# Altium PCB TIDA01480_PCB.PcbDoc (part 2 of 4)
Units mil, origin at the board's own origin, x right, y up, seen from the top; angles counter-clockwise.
Board outline 2500 x 3500 mil, 6 copper layers (Top Layer, GND Upper, Signal Layer 1, Signal Layer 2, GND Lower, Bottom Layer), stack 63.4 mil thick; 332 components, 140 nets, 983 pads, 692 vias.
Unrouted connection lines stored in the file: 17.
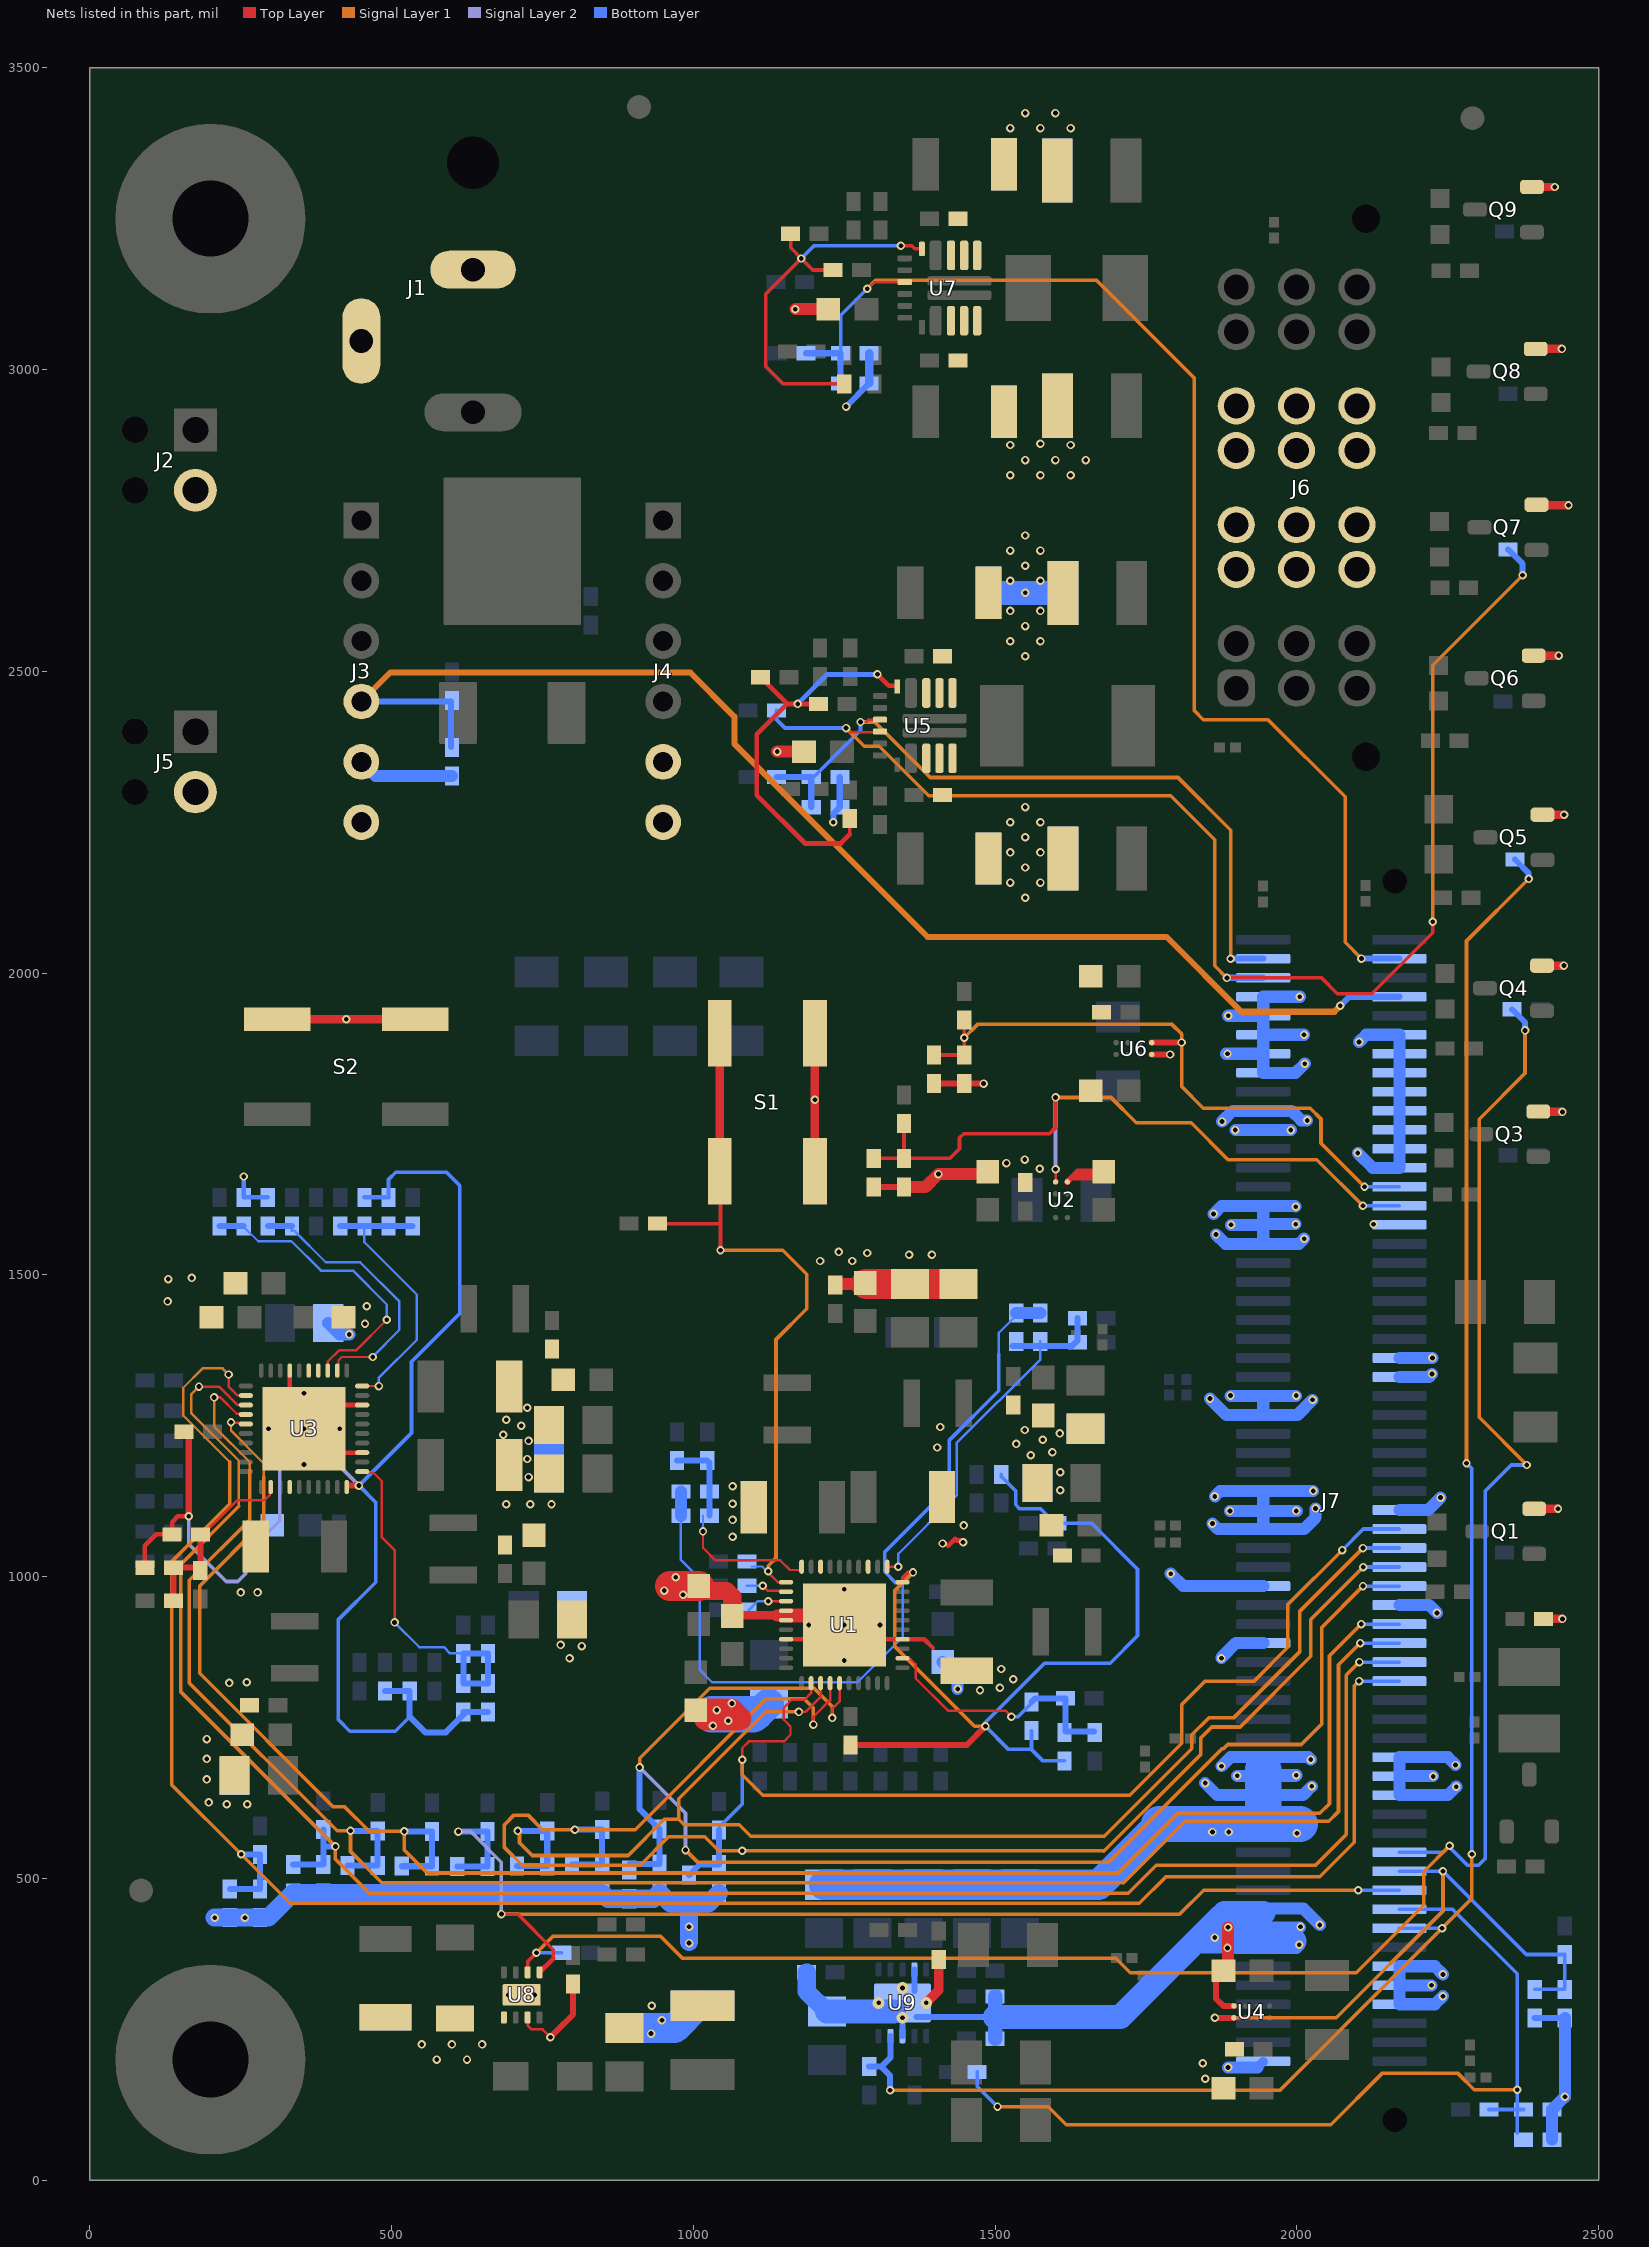
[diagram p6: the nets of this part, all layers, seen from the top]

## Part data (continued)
C7 C32 C114 C115: library part CMP-0006824-2, "CAP, CERM, 1 uF, 16 V, +/- 20%, X5R, 0603", Cap_Case=0603, Manufacturer="Wurth Elektronik", Supplier Part Number 1=710-885012106017, TempCo=X5R, Tolerance_%=20%, Value1=Unknown, Value2=16V, ValueDisplayed=1uF
C8 C12 C13 C33 C34 C35 C52 C53 C54 C55 C69 C70 C71 C72 C82 C83: library part CMP-0009116-1, "CAP, CERM, 22 uF, 16 V, +/- 10%, X7R, 1210", Cap_Case=1210_280, Manufacturer=TDK, Supplier Part Number 1=445-3945-1-ND, TempCo=X7R, Tolerance_%=10%, Value1="0.002582 ohm", Value2=16V, ValueDisplayed=22uF
C10 C41 C65: library part CMP-0064927-2, "CAP, CERM, 1 uF, 10 V,+/- 20%, X5R, 0402", Cap_Case=0402, Manufacturer=MuRata, Supplier Part Number 1=490-5409-1-ND, TempCo=X5R, Tolerance_%=20%, Value1=Unknown, Value2=10V, ValueDisplayed=1uF
C11 C42 C66: library part CMP-0007503-3, "CAP, CERM, 4.7 uF, 6.3 V, +/- 10%, X7R, 0603", Cap_Case=0603, Manufacturer="Taiyo Yuden", TempCo=X7R, Tolerance_%=10%, Value1=Unknown, Value2=6.3V, ValueDisplayed=4.7uF
C22 C47: library part CMP-0006678-2, "CAP, CERM, 1500 pF, 50 V, +/- 10%, X7R, 0402", Cap_Case=0402, Manufacturer=MuRata, Supplier Part Number 1=490-3245-1-ND, TempCo=X7R, Tolerance_%=10%, Value1=Unknown, Value2=50V, ValueDisplayed=1500pF
C25 C50: library part CMP-0007690-2, "CAP, CERM, 4.7 uF, 10 V, +/- 10%, X7R, 0805", Cap_Case=0805, Manufacturer="Wurth Elektronik", Supplier Part Number 1=710-885012207025, TempCo=X7R, Tolerance_%=10%, Value1=Unknown, Value2=10V, ValueDisplayed=4.7uF
C51 C56 C57 C68 C73 C74: library part CMP-0006295-2, "CAP, CERM, 0.1 uF, 25 V, +/- 20%, X7R, 0402", Cap_Case=0402, Manufacturer=TDK, Supplier Part Number 1=445-7349-1-ND, TempCo=X7R, Tolerance_%=20%, Value1=Unknown, Value2=25V, ValueDisplayed=0.1uF
C58 C59 C60 C61 C75 C76 C77 C78 C90 C91: library part CMP-0009220-2, "CAP, CERM, 47 uF, 10 V, +/- 10%, X7R, 1210", Cap_Case=1210, Manufacturer=MuRata, Supplier Part Number 1=490-5312-1-ND, TempCo=X7R, Tolerance_%=10%, Value1=Unknown, Value2=10V, ValueDisplayed=47uF
C62 C79: library part CMP-0006388-2, "CAP, CERM, 47 pF, 25 V, +/- 5%, C0G/NP0, 0402", Cap_Case=0402, Manufacturer=MuRata, Supplier Part Number 1=81-GRM1555C1E470JA1D, TempCo=C0G/NP0, Tolerance_%=5%, Value1=Unknown, Value2=25V, ValueDisplayed=47pF
C63 C80: library part CMP-0007105-5, "CAP, CERM, 4.7 uF, 10 V, +/- 10%, X5R, 0603", Cap_Case=0603, Manufacturer=TDK, Supplier Part Number 1=445-7482-1-ND, TempCo=X5R, Tolerance_%=10%, Value1=Unknown, Value2=10V, ValueDisplayed=4.7uF
C67 C81: library part CMP-0006298-2, "CAP, CERM, 0.047 uF, 50 V, +/- 10%, X7R, 0402", Cap_Case=0402, Manufacturer=TDK, Supplier Part Number 1=445-7336-1-ND, TempCo=X7R, Tolerance_%=10%, Value1="0.06407 ohm", Value2=50V, ValueDisplayed=0.047uF
C84: library part CMP-0008692-2, "CAP, CERM, 10 uF, 25 V, +/- 20%, X7R, 1206_190", Cap_Case=1206, Manufacturer=TDK, Supplier Part Number 1=445-6812-1-ND, TempCo=X7R, Tolerance_%=20%, Value1=Unknown, Value2=25V, ValueDisplayed=10uF
C85 C86 C87 C97 C98: library part CMP-0008311-2, "CAP, CERM, 10 uF, 6.3 V, +/- 10%, X7R, 0805", Cap_Case=0805, Manufacturer=MuRata, Supplier Part Number 1=490-3904-1-ND, TempCo=X7R, Tolerance_%=10%, Value1=Unknown, Value2=6.3V, ValueDisplayed=10uF
C92: library part CMP-0008283-2, "CAP, CERM, 4.7 uF, 6.3 V, +/- 10%, X5R, 0805", Cap_Case=0805, Manufacturer=MuRata, Supplier Part Number 1=GRM21BR60J475KA11L-ND, TempCo=X5R, Tolerance_%=10%, Value1=Unknown, Value2=6.3V, ValueDisplayed=4.7uF
C93: library part CMP-0006348-2, "CAP, CERM, 22 pF, 50 V, +/- 5%, C0G/NP0, AEC-Q200 Grade 1, 0402", Cap_Case=0402, Manufacturer=MuRata, Supplier Part Number 1=490-9648-1-ND, TempCo=C0G/NP0, Tolerance_%=5%, Value1=Unknown, Value2=50V, ValueDisplayed=22pF
C94: library part CMP-0006408-2, "CAP, CERM, 10 pF, 50 V, +/- 5%, C0G/NP0, 0402", Cap_Case=0402, Manufacturer=MuRata, Supplier Part Number 1=81-GRM1555C1H100JA1D, TempCo=C0G/NP0, Tolerance_%=5%, Value1=Unknown, Value2=50V, ValueDisplayed=10pF
C96: library part CMP-0006296-2, "CAP, CERM, 1000 pF, 50 V, +/- 20%, X7R, 0402", Cap_Case=0402, Manufacturer=TDK, Supplier Part Number 1=445-173775-1-ND, TempCo=X7R, Tolerance_%=20%, Value1=Unknown, Value2=50V, ValueDisplayed=1000pF
C99 C100 C101 C102: library part CMP-0006406-2, "CAP, CERM, 910 pF, 25 V, +/- 5%, C0G/NP0, 0402", Cap_Case=0402, Manufacturer=MuRata, Supplier Part Number 1=GRM1555C1E911JA01D-ND, TempCo=C0G/NP0, Tolerance_%=5%, Value1=Unknown, Value2=25V, ValueDisplayed=910pF
C103 C106 C107: library part CMP-0006393-2, "CAP, CERM, 510 pF, 25 V, +/- 5%, C0G/NP0, 0402", Cap_Case=0402, Manufacturer=MuRata, Supplier Part Number 1=GRM1555C1E511JA01D-ND, TempCo=C0G/NP0, Tolerance_%=5%, Value1=Unknown, Value2=25V, ValueDisplayed=510pF
C104 C108 C111 C112: library part CMP-0006410-2, "CAP, CERM, 100 pF, 50 V, +/- 5%, C0G/NP0, 0402", Cap_Case=0402, Manufacturer=MuRata, Supplier Part Number 1=81-GRM1555C1H101JA1D, TempCo=C0G/NP0, Tolerance_%=5%, Value1=Unknown, Value2=50V, ValueDisplayed=100pF
C105 C109 C110 C113: library part CMP-0064916-2, "CAP, CERM, 10 pF, 50 V,+/- 1%, C0G/NP0, 0402", Cap_Case=0402, Manufacturer=MuRata, Supplier Part Number 1=490-6186-1-ND, TempCo=C0G/NP0, Tolerance_%=1%, Value1=Unknown, Value2=50V, ValueDisplayed=10pF
D1: library part CMP-0028356-1, "Diode, Schottky, 40 V, 12 A, DPAK", Manufacturer=Vishay-Semiconductor, Supplier Part Number 1=844-12CWQ04FNPBF, Value1=12A, Value2=0.68V
D2: library part CMP-0002884-1, "LED, Cool White, SMD", Color="cool white", Manufacturer=Panasonic, Supplier Part Number 1=LNJ037X8ARACT-ND, Value1=W, Value2=2.9V
D3: library part CMP-0067668-1, "LED, Red, SMD", Color=Red, Manufacturer=Vishay-Semiconductor, Power_TotalModule=200mW, Supplier Part Number 1=VLMR334BACB-GS08CT-ND, Value1=0.2W, Value2=2.2V
D4 D7 D8 D9 D10: "LED, Green, SMD", Color=green, Manufacturer=Lite-On, Supplier Part Number 1=160-1435-1-ND, Value1=W, Value2=2V
D5: "LED, Orange, SMD", Color=orange, Manufacturer=Lite-On, Power_TotalModule=0.075, Supplier Part Number 1=160-1434-1-ND, Value1=0.075W, Value2=2V
D6: library part CMP-0002862-1, "LED, Yellow , SMD", Color=yellow, Manufacturer=Lite-On, Supplier Part Number 1=160-1416-1-ND, Value1=W, Value2=2V
FID1 FID2 FID3: "Fiducial mark.  There is nothing to buy or mount.", Manufacturer=N/A
H1 H2: "Machine Screw, Round, #4-40 x 1/4, Nylon, Philips panhead", DigiKeyPartNumber=H542-ND, Manufacturer="B&F Fastener Supply"
H3 H4: "Standoff, Hex, 0.5\"L #4-40 Nylon", Manufacturer=Keystone, Supplier Part Number 1=36-1902C-ND
J1: library part CMP-0075310-1, "Connector, DC Jack 2.5 mm Center Pin, TH", Color=Black, Current_A=2.5A, Manufacturer="CUI Inc.", Supplier Part Number 1=CP-058B-ND, Voltage_V=24V
J2 J5: library part CMP-0055479-1, "Terminal Block, 100mil, 2x1, 6A, 63V, TH", Manufacturer="Phoenix Contact", Supplier Part Number 1=71C4107
J3 J4: library part CMP-0055084-1, "Header, 100mil, 6x1, TH", Manufacturer=Mill-Max, Supplier Part Number 1=ED7206-ND
J6: library part CMP-0078461-1, "Receptacle, 5mm, 4x1, Gold with Tin tail, TH", Color=Black, Current_A=30A, Manufacturer=Samtec, Supplier Part Number 1=SAM9721-ND, Voltage_V=812V
J7: library part CMP-0078459-1, "Socket Assembly, 0.8mm, 60x2, Gold, SMT", Color=Black, Manufacturer=Samtec, Supplier Part Number 1=SAM9181-ND
L1 L2 L3 L4 L5 L6: library part CMP-0062881-1, "Inductor, Film, 2.2 uH, 2.6 A, 0.084 ohm, AEC-Q200 Grade 0, SMD", Manufacturer=TDK, Value1="0.084 ohm", Value2=2.6A, ValueDisplayed=2.2uH
L7: library part CMP-0063396-1, "Inductor, Shielded Drum Core, Powdered Iron, 470 nH, 17.5 A, 0.004 ohm, SMD", Manufacturer=Vishay-Dale, Supplier Part Number 1=541-1003-1-ND, Value1="0.004 ohm", Value2=17.5A, ValueDisplayed=470nH
L8: library part CMP-0063307-1, "Inductor, Shielded Drum Core, Powdered Iron, 470 nH, 11.5 A, 0.0081 ohm, SMD", Manufacturer=Vishay-Dale, Supplier Part Number 1=541-1085-1-ND, Value1="0.0081 ohm", Value2=11.5A, ValueDisplayed=470nH
L9: library part CMP-0063238-1, "Inductor, Shielded Drum Core, Powdered Iron, 1 uH, 3 A, 0.038 ohm, SMD", Manufacturer=Vishay-Dale, Value1="0.038 ohm", Value2=3A, ValueDisplayed=1uH
Logo1: library part TI_Logo, "Texas Instrument Corporate Signature"
Logo2: library part Pb-Free
Logo3: library part FCC_disclaimer, "FCC_disclaimer"
Q1 Q3 Q4 Q5 Q6 Q7 Q8 Q9: "MOSFET, N-CH, 60V, 0.17A, SOT-23", Alternate Manufacturer=None, Manufacturer="Diodes Inc.", Supplier Part Number 1=2N7002-FDICT-ND, Value1="7.5 ohm", Value2="223 nC"
Q2: library part CMP-0000011-2, "MOSFET, P-CH, -50 V, -0.13 A, SOT-23", Alternate Manufacturer=None, Manufacturer="Diodes Inc.", Supplier Part Number 1=BSS84-FDICT-ND
R1 R30: library part CMP-0025963-2, "RES, 10.0, 1%, 0.063 W, 0402", Manufacturer=Vishay-Dale, Power_W=63mW, Supplier Part Number 1=541-10.0LCT-ND, TempCo="100 ppm/C", Tolerance_%=1%, Value2=0.063W, Value_Code=10R0, ValueDisplayed=10.0
R2 R33 R62 R66 R67 R68 R69 R70 R71 R78 R135 R136: library part CMP-0018573-2, "RES, 0, 5%, 0.25 W, 1206", Manufacturer=Vishay-Dale, Power_W=250mW, Supplier Part Number 1=541-0.0ECT-ND, TempCo="200 ppm/C", Tolerance_%=5%, Value2=0.25W, Value_Code=0000, ValueDisplayed=0
R3 R4 R31 R32: library part CMP-0026952-4, "RES, 5.6 k, 5%, 0.063 W, 0402", Manufacturer=Vishay-Dale, Power_W=63mW, Supplier Part Number 1=541-5.6KJCT-ND, TempCo="200 ppm/C", Tolerance_%=5%, Value2=0.063W, Value_Code=5k60, ValueDisplayed=5.6k
R5 R6 R18 R19 R20 R25 R27 R28 R36 R37 R39 R41 R51 R52 R53 R57 R58 R59: library part CMP-0026964-2, "RES, 68, 5%, 0.063 W, 0402", Manufacturer=Vishay-Dale, Power_W=63mW, Supplier Part Number 1=541-68JCT-ND, TempCo="200 ppm/C", Tolerance_%=5%, Value2=0.063W, Value_Code=68R0, ValueDisplayed=68
R7: library part CMP-0025959-2, "RES, 10.2 k, 1%, 0.063 W, 0402", Manufacturer=Vishay-Dale, Power_W=63mW, Supplier Part Number 1=541-10.2KLCT-ND, TempCo="100 ppm/C", Tolerance_%=1%, Value2=0.063W, Value_Code=10k2, ValueDisplayed=10.2k
R8 R10 R38 R43 R82 R84 R87 R88 R89 R94 R99 R156: library part CMP-0026823-2, "RES, 100 k, 5%, 0.063 W, 0402", Manufacturer=Vishay-Dale, Power_W=63mW, Supplier Part Number 1=541-100KJCT-ND, TempCo="200 ppm/C", Tolerance_%=5%, Value2=0.063W, Value_Code=100k
R9 R15 R22 R23 R26 R35 R42 R48 R55 R63 R74: library part CMP-0026815-1, "RES, 100 k, 0.1%, 0.063 W, 0402", Manufacturer="Susumu Co Ltd", Power_W=63mW, Supplier Part Number 1=RG10P100KBCT-ND, TempCo="25 ppm/C", Tolerance_%=0.1%, Value2=0.063W, Value_Code=100k
R11 R12 R13 R14 R44 R45 R46 R47 R60 R72 R80 R90 R91 R92 R95 R96 R100 R155: library part CMP-0026825-4, "RES, 10 k, 5%, 0.063 W, 0402", Manufacturer=Vishay-Dale, Power_W=63mW, Supplier Part Number 1=541-10KJCT-ND, TempCo="200 ppm/C", Tolerance_%=5%, Value2=0.063W, Value_Code=10k0, ValueDisplayed=10k
R16 R49 R54 R56: library part CMP-0026158-1, "RES, 200 k, 1%, 0.063 W, 0402", Manufacturer=Vishay-Dale, Power_W=63mW, Supplier Part Number 1=541-200KLCT-ND, TempCo="100 ppm/C", Tolerance_%=1%, Value2=0.063W, Value_Code=200k
R17: library part CMP-0026176-1, "RES, 226 k, 1%, 0.063 W, 0402", Manufacturer=Vishay-Dale, Power_W=63mW, Supplier Part Number 1=541-226KLCT-ND, TempCo="100 ppm/C", Tolerance_%=1%, Value2=0.063W, Value_Code=226k
R21: library part CMP-0026288-1, "RES, 316 k, 1%, 0.063 W, 0402", Manufacturer=Vishay-Dale, Power_W=63mW, Supplier Part Number 1=541-316KLCT-ND, TempCo="100 ppm/C", Tolerance_%=1%, Value2=0.063W, Value_Code=316k
R24 R61 R73: library part CMP-0026702-1, "RES, 49.9 k, 1%, 0.1 W, AEC-Q200 Grade 0, 0402", Manufacturer=Panasonic, Power_W=100mW, Supplier Part Number 1=P49.9KLCT-ND, TempCo="100 ppm/C", Tolerance_%=1%, Value2=0.1W, Value_Code=49k9, ValueDisplayed=49.9k
R29 R81 R85 R93 R97 R98 R101: library part CMP-0026822-2, "RES, 0, 5%, 0.063 W, 0402", Manufacturer=Vishay-Dale, Power_W=63mW, Supplier Part Number 1=541-0.0JCT-ND, TempCo="200 ppm/C", Tolerance_%=5%, Value2=0.063W, Value_Code=0000, ValueDisplayed=0
R34: library part CMP-0026196-1, "RES, 24.9 k, 1%, 0.063 W, 0402", Manufacturer=Vishay-Dale, Power_W=63mW, Supplier Part Number 1=541-24.9KLCT-ND, TempCo="100 ppm/C", Tolerance_%=1%, Value2=0.063W, Value_Code=24k9, ValueDisplayed=24.9k
R40: library part CMP-0026502-1, "RES, 66.5 k, 1%, 0.063 W, 0402", Manufacturer=Vishay-Dale, Power_W=63mW, Supplier Part Number 1=541-66.5KLCT-ND, TempCo="100 ppm/C", Tolerance_%=1%, Value2=0.063W, Value_Code=66k5, ValueDisplayed=66.5k
R50: library part CMP-0026789-1, "RES, 86.6 k, 0.1%, 0.063 W, AEC-Q200 Grade 0, 0402", Manufacturer=Panasonic, Power_W=63mW, Supplier Part Number 1=P86.6KDCCT-ND, TempCo="25 ppm/C", Tolerance_%=0.1%, Value2=0.063W, Value_Code=86k6, ValueDisplayed=86.6k
R64 R65 R75 R76: library part CMP-0026437-1, "RES, 51.1 k, 1%, 0.063 W, 0402", Manufacturer=Vishay-Dale, Power_W=63mW, Supplier Part Number 1=541-51.1KLCT-ND, TempCo="100 ppm/C", Tolerance_%=1%, Value2=0.063W, Value_Code=51k1, ValueDisplayed=51.1k
R77 R79: library part CMP-0065360-1, "RES, 10.0 k, .1%, .0625 W, 0402", Manufacturer="Yageo America", Power_W=62.5mW, Supplier Part Number 1=YAG1346CT-ND, TempCo="25 ppm/C", Tolerance_%=0.1%, Value1=.1%, Value2=.0625W, Value_Code=10k0, ValueDisplayed=10.0k
R83: library part CMP-0026712-1, "RES, 97.6 k, 1%, 0.1 W, AEC-Q200 Grade 0, 0402", Manufacturer=Panasonic, Power_W=100mW, Supplier Part Number 1=P97.6KLCT-ND, TempCo="100 ppm/C", Tolerance_%=1%, Value2=0.1W, Value_Code=97k6, ValueDisplayed=97.6k
R86: library part CMP-0026787-1, "RES, 76.8 k, 0.1%, 0.063 W, AEC-Q200 Grade 0, 0402", Manufacturer=Panasonic, Power_W=63mW, Supplier Part Number 1=P76.8KDCCT-ND, TempCo="25 ppm/C", Tolerance_%=0.1%, Value2=0.063W, Value_Code=76k8, ValueDisplayed=76.8k
R102 R103 R104 R105 R106 R107 R108 R109 R110 R111 R112 R113 R114 R115 R116 R157: library part CMP-0026859-1, "RES, 1.0 M, 5%, 0.063 W, 0402", Manufacturer=Vishay-Dale, Power_W=63mW, Supplier Part Number 1=541-1.0MJCT-ND, TempCo="200 ppm/C", Tolerance_%=5%, Value2=0.063W, Value_Code=1M00, ValueDisplayed=1.0M
R117: library part CMP-0026882-2, "RES, 240, 5%, 0.063 W, 0402", Manufacturer=Vishay-Dale, Power_W=63mW, Supplier Part Number 1=541-240JCT-ND, TempCo="200 ppm/C", Tolerance_%=5%, Value2=0.063W, Value_Code=240R, ValueDisplayed=240
R118: library part CMP-0078194-1, "RES, 360, 5%, 0.1 W, AEC-Q200 Grade 0, 0402", Manufacturer=Panasonic, Power_W=100mW, Supplier Part Number 1=P360JCT-ND, TempCo="200 ppm/C", Tolerance_%=5%, Value2=0.1W, Value_Code=360R, ValueDisplayed=360
R119 R120 R122 R129 R130 R131: library part CMP-0026841-2, "RES, 150, 5%, 0.063 W, 0402", Manufacturer=Vishay-Dale, Power_W=63mW, Supplier Part Number 1=541-150JCT-ND, TempCo="200 ppm/C", Tolerance_%=5%, Value2=0.063W, Value_Code=150R, ValueDisplayed=150
R121: library part CMP-0026845-2, "RES, 160, 5%, 0.063 W, 0402", Manufacturer=Vishay-Dale, Power_W=63mW, Supplier Part Number 1=541-160JCT-ND, TempCo="200 ppm/C", Tolerance_%=5%, Value2=0.063W, Value_Code=160R, ValueDisplayed=160
R123 R124 R125 R126 R127 R128 R132 R133 R134: library part CMP-0027004-2, "RES, 0, 5%, 0.063 W, 0402", Manufacturer="Yageo America", Power_W=63mW, Supplier Part Number 1=311-0.0JRCT-ND, TempCo="200 ppm/C", Tolerance_%=5%, Value2=0.063W, Value_Code=0000, ValueDisplayed=0
R137 R138 R139 R140 R141 R142 R143 R144 R145 R146 R147 R148 R149 R150 R151 R152 R153 R154: library part CMP-0027008-3, "RES, 0, 5%, 0.05 W, 0201", Manufacturer=Vishay-Dale, Power_W=50mW, Supplier Part Number 1=72M6743, TempCo=ppm/C, Tolerance_%=5%, Value2=0.05W, Value_Code=0000, ValueDisplayed=0
S1 S2: library part CMP-0002132-2, "Switch, Tactile, SPST-NO, SMT", CurrentRating_mA=50A, Manufacturer="C&K Components", Supplier Part Number 1=401-1848-1-ND
U1 U3: library part CMP-0074190-1, "6-channel Power Management IC (PMIC) with 3DC/DCs, 3 LDOs, I2C Interface and DVS, RSB0040B (WQFN-40)", Alternate Manufacturer="Texas Instruments", Alternate PartNumber=TPS65023BRSBT
U2 U4 U6: library part CMP-0066647-2, "3.6V, 4A, 5.3mO Load Switch with Quick Output Discharge, YZP0008ADCD (DSBGA-8)", Alternate Manufacturer="Texas Instruments", Alternate PartNumber=TPS22920YZPT
U5: library part CMP-0074013-1, "4.5V to 17V Input, DCAP3 Mode, 12A Synchronous Step-Down SWIFT(TM) Converter, RNN0018A (VQFN-HR-18)", Alternate Manufacturer="Texas Instruments", Alternate PartNumber=TPS56C215RNNT
U7: library part CMP-0074010-1, "4.5V to 17V Input, DCAP3 Mode, 8A Synchronous SWIFT(TM) Step-Down Converter, RNN0018A (VQFN-HR-18)", Alternate Manufacturer="Texas Instruments", Alternate PartNumber=TPS568215RNNT
U8: library part CMP-0037738-2, "Buck Step Down Regulator with 2.9 to 6 V Input and 0.8 to 6 V Output, -40 to 85 degC, 8-Pin WSON (DSG), Green (RoHS & no Sb/Br)", Manufacturer="Texas Instruments", Rating=Catalog, Switch Current Limit(Typ)(A)=2.75
U9: library part CMP-0036438-2, "Single Output LDO, 3 A, 2.375 to 3.5 V Input, with DDR Termination, 10-pin SON (DRC), -40 to 85 degC, Green (RoHS & no Sb/Br)", Manufacturer="Texas Instruments", Power Good=TRUE, Rating=Catalog
ZZ1: library part AssemblyNoteLabel
ZZ2 ZZ3 ZZ4: library part AssemblyNote

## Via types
v1: diameter 14, hole 7.9, Top Layer to Bottom Layer, tented both sides, 676 vias
v2: diameter 19.68, hole 7.87, Top Layer to Bottom Layer, 16 vias

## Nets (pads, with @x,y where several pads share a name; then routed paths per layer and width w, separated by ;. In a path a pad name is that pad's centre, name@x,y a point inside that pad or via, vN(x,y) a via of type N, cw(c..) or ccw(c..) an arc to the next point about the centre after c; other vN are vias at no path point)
AGND: C22.2 C47.2 C67.2 C81.2 R9.1 R22.1 R23.1 R24.1 R25.1 R26.1 R27.1 R28.1 R35.1 R42.1 R54.1 R55.1 R56.1 R57.1 R58.1 R59.1 R63.1 R65.1 R74.1 R76.1 R86.1 U5.12 U7.12 | length 6749.6
  Top Layer w6: R74.1@1161.38,3225 1161.38,3201.62 v1(1179,3184) ; C81.2@1231.59,3165 1198,3165 v1(1179,3184) ; R76.1@1250,2976.38 1148.62,2976.38 1120,3005 1120,3125 v1(1179,3184) ; 1259.27,2229.73 R65.1@1259.27,2256.38 ; 1344,3205 1362,3205 1367.04,3199.96 U7.12@1378.8,3199.96
  Top Layer w7.6: R58.1@91.38,1015 91.38,1051.38 110,1070 R55.1@136.38,1070 136.38,1090.38 146,1100 v1(164,1100)
  Top Layer w8: R63.1@1111.38,2490 1155.38,2446 ; C67.2@1207.38,2446 v1(1173,2446) 1155.38,2446 ; 1259.27,2229.73 1244.54,2215 1185,2215 1105,2295 1105,2395.62 1155.38,2446 ; 1305,2495 1323.99,2476.01 1337.85,2476.01 U5.12@1337.85,2474.96
  Top Layer w10: C47.2@156.38,1240 164,1232.38 v1(164,1100) ; 763.15,237.05 773.05,246.95 800.63,274.53 R86.1@800.63,325.09 ; C22.2@1260.22,721.38 1453.38,721.38 v1(1484,752)
  Signal Layer 1 w6: 1364,1007 1334,977 1334,884 1466,752 v1(1484,752)
  Signal Layer 2 w6: v1(164,1100) 164,1054 226,992 245,992 258,1005 258,1035.65 315,1092.65 315,1180 345,1210 387,1210 446,1151
  Bottom Layer w4: R25.1@979.38,1101 979.38,1027.62 1010.87,996.13 1010.87,845.13 1031,825 1272,825 1347,900 1347,990 1364,1007 ; 1506,1369 1506,1404 1535,1433 R28.1@1535,1436.97
  Bottom Layer w6: R57.1@495,1628.62 495,1658 507,1670 591,1670 613,1648 613,1436 533,1356 533,1238 446,1151 474,1123 474,991 412,929 412,763 431,744 506,744 530,768 ; v1(1179,3184) 1200,3205 1344,3205 ; 1347,990 1335,990 1317,1008 1317,1041 1424.32,1148.32 1424.32,1226.29 1506,1307.97 1506,1369 ; R9.1@1510,1169.62 1510,1166 1534.13,1141.87 1534.13,1119 1540.5,1112.63 1575.37,1112.63 R26.1@1599.46,1088.54 ; R23.1@1560.22,744.76 1560.22,713.78 ; R26.1@1602.62,1088.54 1659.91,1088.54 1736,1012.45 1736,902 1690.72,856.72 1582,856.72 1484,758.72 v1(1484,752) 1522.22,713.78 1560.22,713.78 ; R27.1@1615,694.76 1579.24,694.76 1560.22,713.78
  Bottom Layer w7.6: R54.1@455,1628.62 R57.1@495,1628.62
  Bottom Layer w8: v1(1173,2446) 1222,2495 1305,2495
  Bottom Layer w10: R42.1@489,810.38 R35.1@530,810.38 530,768 556,742 590,742 619,771 R59.1@619,776 R56.1@660,776
  Bottom Layer w20: R25.1@979.38,1101 R22.1@979.38,1141 ; R28.1@1535,1436.97 R24.1@1575,1436.97
BUCK_1or2A_EN: C103.1 J7.20 R91.2 R106.2 U8.5 | length 1995.8
  Top Layer w6: v1(682,441) 709,441 768,382 768,367.33
  Top Layer w8: U8.5@745.16,344.49 768,367.33
  Signal Layer 1 w6: v1(682,441) 1806,441 1845.51,480.51 v1(2101.51,480.51)
  Signal Layer 2 w6: v1(610.76,577.76) 631.24,577.76 682,527 v1(682,441)
  Bottom Layer w6: v1(2101.51,480.51) J7.20@2169.74,480.51
  Bottom Layer w10: R106.2@609,520 C103.1@659,520 R91.2@659,577.76 v1(610.76,577.76)
BUCK_8A_EN: C104.1 J7.118 R92.2 R107.2 U7.15 | length 2115.2
  Top Layer w4: v1@1289.36,3134 1300.2,3144.84 U7.15@1350.26,3144.84
  Signal Layer 1 w6: v1(1288,3134) 1302,3148 1668,3148 1830,2986 1830,2435 1845,2420 1952,2420 2080,2292 2080,2051 v1(2107,2024)
  Bottom Layer w6: C104.1@1244.09,3027 1244.09,3090.09 v1(1288,3134)
  Bottom Layer w10: R92.2@1186.34,3027 C104.1@1244.09,3027 R107.2@1244.09,2977 ; v1@2107.18,2023.82 J7.118@2169.74,2023.82
BUCK_12A_EN: C105.1 J7.117 R93.1 R108.2 U5.15 | length 1219.5
  Top Layer w4: v1(1277,2416) 1286.32,2416 1290.16,2419.84 U5.15@1309.31,2419.84
  Signal Layer 1 w6: v1(1277,2416) 1300.36,2416 1392.36,2324 1803,2324 1890.18,2236.82 v1(1890.18,2023.82)
  Bottom Layer w6: C105.1@1199.28,2324.83 1277,2402.55 v1(1277,2416)
  Bottom Layer w10: R93.1@1137.62,2324.83 C105.1@1195.38,2324.83 R108.2@1195.38,2274.83 ; v1(1890.18,2023.82) J7.117@1944.26,2023.82
DCDC1_EN_A: C112.1 J7.52 R100.2 R115.2 U1.25 | length 2345.5
  Top Layer w4: v1(1230,766) 1230,781 1242.34,793.34 U1.25@1242.34,823.54
  Signal Layer 1 w6: v1@911,685 911,699 1027,815 1200,815 1230,785 v1(1230,766) ; v1@991,547 v1(987,547) 1006.87,527.13 1688.13,527.13 1875.61,714.61 1877.92,714.61 1885.32,722 2007.24,722 2041,755.76 2041,915.9 v1(2109.55,984.45)
  Signal Layer 2 w6: v1(911,684) 987,608 v1(987,547)
  Bottom Layer w6: v1(2109.55,984.45) J7.52@2169.74,984.45
  Bottom Layer w10: R115.2@894,524 C112.1@944,524 R100.2@944,581.76 911,614.76 v1(911,684)
DCDC1_EN_B: C108.1 J7.48 R96.2 R111.2 U3.25 | length 3119.1
  Top Layer w4: v1@235.19,1254.81 252.86,1254.81 256.67,1251 U3.25@258.54,1252.87
  Signal Layer 1 w4: v1(234,1256) 234,1242 288,1188 288,1166
  Signal Layer 1 w6: 288,1166 288,1090.7 182,984.7 182,840 403,619 422,619 463,578 v1(521,578) 521,547 559,509 1704,509 1803,608 2038,608 2054,624 2054,869 v1(2106.46,921.46)
  Bottom Layer w6: v1(2106.46,921.46) J7.48@2169.74,921.46
  Bottom Layer w10: R111.2@517,520.24 C108.1@567,520.24 R96.2@567,578 v1(521,578)
DCDC2_EN_A: C111.1 J7.54 R99.2 R114.2 U1.24 | length 2693.7
  Top Layer w4: v1(1199,755) 1199,768 1226.59,795.59 U1.24@1226.59,823.54
  Signal Layer 1 w6: v1(1199,755) 1199,782 1183,798 1121,798 903.76,580.76 v1(803.76,580.76) 750.24,580.76 726,605 703,605 687,589 687,551.38 716.38,522 912,522 959,569 1019,569 1042,546 v1(1081,546) 1679,546 1680,545 1841,706 1841,733 1859,751 1906,751 2023,868 2023,928.89 v1(2110.06,1015.94)
  Bottom Layer w6: v1(2110.06,1015.94) J7.54@2169.74,1015.94
  Bottom Layer w10: R114.2@799,523 C111.1@849,523 R99.2@849,580.76 v1(803.76,580.76)
DCDC2_EN_B: C107.1 J7.46 R95.2 R110.2 U3.24 | length 3224.6
  Top Layer w4: v1(206,1297) 216.44,1297 243.44,1270 257.17,1270 U3.24@258.54,1268.62
  Signal Layer 1 w4: v1(206,1297) 206,1249 265,1190 265,1177
  Signal Layer 1 w6: 265,1177 265,1094 165,994 165,824 410,579 v1(432,579) 432,544.62 483.62,493 1713,493 1815,595 2053,595 2069,611 2069,853.92 v1(2105.04,889.96)
  Bottom Layer w6: v1(2105.04,889.96) J7.46@2169.74,889.96
  Bottom Layer w10: R110.2@427,521.24 C107.1@477,521.24 R95.2@477,579 v1(432,579)
DCDC3_EN_A: C110.1 J7.56 R98.1 R113.2 U1.23 | length 2293.4
  Top Layer w4: v1(1175,776) 1186,776 1210.85,800.85 U1.23@1210.85,823.54
  Signal Layer 1 w6: v1@712,581 712,559 733,538 892,538 952,598 976,598 ; v1(1175,776) 1120,776 976,632 976,598 ; v1(2109.44,1047.44) 2005,943 2005,876 1895,766 1854,766 1826,738 1826,715 1681,570 1095,570 1076,589 985,589 976,598
  Bottom Layer w6: v1(2109.44,1047.44) J7.56@2169.74,1047.44
  Bottom Layer w10: R113.2@708,521 C110.1@758,521 R98.1@758,578.76 v1(709.24,578.76)
DCDC3_EN_B: C106.1 J7.44 R94.2 R109.2 U3.23 | length 3283.1
  Top Layer w4: v1(181,1315) 214,1315 244.63,1284.37 U3.23@258.54,1284.37
  Signal Layer 1 w4: v1(181,1315) 168,1302 168,1270.97 247,1191.97 247,1116.44
  Signal Layer 1 w6: 247,1116.44 151,1020.44 151,809 v1(407,553) 407,532 463.4,475.6 1720.6,475.6 1767,522 2031,522 2082,573 2082,836.93 v1(2103.54,858.46)
  Bottom Layer w6: v1(2103.54,858.46) J7.44@2169.74,858.46
  Bottom Layer w10: R109.2@337,522.99 C106.1@387,522.99 R94.2@387,580.74 ; 388.13,553 v1(407,553)
DDR_Strt_PG: J7.24 R84.2 R126.1 U8.6 | length 3438.4
  Top Layer w6: U8.6@725.47,344.49 725.47,362.47 v1@740,377
  Signal Layer 1 w6: v1(740.09,377.09) 767,404 946,404 982,368 1700,368 1724,344 2098.26,344 2210,455.74 2210,511 v1(2253,554) ; v1(2378,1905) 2378,1834 2302,1758 2302,1264 v1(2381,1185)
  Bottom Layer w6: v1(740.09,377.09) R84.2@782.01,377.09 ; J7.24@2169.74,543.5 2242.5,543.5 v1(2253,554) 2253,551.72 2282.72,522 2301,522 2312,533 2312,1142 2355,1185 v1(2381,1185)
  Bottom Layer w10: R126.1@2356.38,1940 2378,1918.38 v1(2378,1905)
DDR_TT_PG: J7.16 R82.2 R127.1 U9.9 | length 3066.5
  Signal Layer 1 w6: v1(1326,149) 1971.96,149 v1(2240.48,417.52) 2290,467.04 v1@2290,541 ; v1(2281,1188) 2281,2053.1 v1(2384,2156.1)
  Bottom Layer w6: J7.16@2169.74,417.52 v1(2240.48,417.52) ; v1(2281,1188) 2290,1179 v1(2290,540)
  Bottom Layer w10: R82.2@1291.48,188.07 1311.2,188.07 ; v1(1326,149) 1326,173.27 1311.2,188.07 ; U9.9@1326.79,238.78 1326.79,203.66 1311.2,188.07 ; R127.1@2361.38,2188.21 2384,2165.59 v1(2384,2156.1)
DEFDCDC1_A: R15.1 R18.1 R22.2 R25.2 U1.10 | length 379.8
  Top Layer w4: v1(1016,1075) 1016,1048 1037,1027 1144,1027 1160,1011 1179,1011 1179,1016.11 U1.10@1179.35,1016.46
  Bottom Layer w4: v1(1016,1075) R25.2@1016,1101
  Bottom Layer w10: R18.1@973,1192.38 R15.1@1023,1192.38 1026.62,1188.76 R22.2@1026.62,1141 R25.2@1026.62,1101
DEFDCDC1_B: R48.1 R51.1 R54.2 R57.2 U3.10 | length 475.3
  Top Layer w4: U3.10@451.46,1315.87 v1(479.13,1315.87)
  Bottom Layer w4: R54.2@455,1581.38 455,1554 542,1467 542,1392.58 479.13,1329.71 v1(479.13,1315.87)
  Bottom Layer w10: R51.1@415,1581.38 R48.1@535,1581.38
DEFDCDC2_A: R16.1 R19.1 R23.2 R27.2 U1.32 | length 438.9
  Top Layer w4: U1.32@1346.67,864.88 1348.61,862.94 1360.27,862.94 1368.36,854.85 1368.36,831.64 1422,778 1517,778 v1(1527,768)
  Bottom Layer w6: v1(1527,768) 1538,768 1560.22,790.22 R23.2@1560.22,792
  Bottom Layer w10: R23.2@1560.22,792 1566.59,798.38 R16.1@1616.59,798.38 1616.59,743.59 R19.1@1663.41,743.59
DEFDCDC2_B: R49.1 R52.1 R55.2 R58.2 U3.32 | length 288.5
  Top Layer w4: R55.2@194.28,1076.28 244.86,1126.86 278.39,1126.86 289.85,1126.86 297.95,1134.95 297.95,1148.54 U3.32@299.88,1148.54
  Top Layer w10: R52.1@138.62,960 R58.2@138.62,1015 R49.1@178.62,1015 ; R49.1@183.62,1020 R55.2@183.62,1070
DEFDCDC3_A: R17.1 R20.1 R24.2 R28.2 U1.1 | length 637.7
  Top Layer w4: U1.1@1321.08,1016.46 v1(1339.54,1016.46)
  Bottom Layer w4: v1(1339.54,1016.46) 1339.54,1037.74 1436.32,1134.51 1436.32,1221.32 1575,1360 R24.2@1575,1389.72
  Bottom Layer w10: R28.2@1529,1382 1627.28,1382 1636.38,1391.1 R20.1@1636.38,1428.35
DEFDCDC3_B: R50.1 R53.1 R56.2 R59.2 U3.1 | length 597.7
  Top Layer w4: U3.1@451.46,1172.13 470,1172.13 484,1158.13 484,1065 505,1044 v1(505,924.15)
  Bottom Layer w4: v1(505,924.15) 545.9,883.24 586.9,883.24 597.14,873 R50.1@619,873
  Bottom Layer w10: R59.2@619,823.24 R56.2@660,823.24 R53.1@660,873 R50.1@619,873 R59.2@619,823.24
DEFLDO1_A: R6.1 U1.12 | length 74.5
  Top Layer w4: v1(1115,985) 1123,977 1151.88,977 U1.12@1153.76,975.12
  Bottom Layer w4: R6.1@1088.62,985 v1(1115,985) v1@1120.24,985
DEFLDO1_B: R36.1 R39.2 U3.12 | length 457.1
  Top Layer w4: U3.12@410.12,1341.46 412.06,1343.39 412.06,1358.5 417.56,1364 v1(469,1364)
  Bottom Layer w4: R36.1@335,1573 R36.1@335,1581.38 ; R36.1@339,1573 391,1521 448,1521 513,1456 513,1409 v1@469,1365
  Bottom Layer w10: R39.2@295,1581.38 R36.1@335,1581.38
DEFLDO2_A: R5.1 U1.13 | length 67.7
  Top Layer w4: v1(1124,959.37) U1.13@1153.76,959.37
  Bottom Layer w4: R5.1@1092,945 1106.37,959.37 v1(1124,959.37)
DEFLDO2_B: R37.1 R41.2 U3.13 | length 497
  Top Layer w4: U3.13@394.37,1341.46 394.37,1356.37 413,1375 441.35,1375 v1(492,1425.65)
  Bottom Layer w4: R41.2@255,1579.85 279.1,1555.76 334.24,1555.76 383,1507 436,1507 492,1451 v1(492,1425.65)
  Bottom Layer w10: R37.1@215,1581.38 R41.2@255,1581.38
EN_DDR_TERM: C102.1 J7.18 R85.2 R90.2 R105.2 | length 1552.7
  Signal Layer 1 w6: v1(1504,122) 1588,122 1618,92 2056,92 2141,177 2267,177 2294,150 v1(2365,150)
  Bottom Layer w6: R85.2@1470.1,179.45 1470.1,155.9 v1(1504,122) ; J7.18@2169.74,449.02 2257.98,449.02 2365,342 v1(2365,150) C102.1@2365,117.21 ; R90.2@2317.99,117.21 C102.1@2365,117.21 ; R105.2@2365,77.95 C102.1@2365,117.21 ; C102.1@2375.74,117.21 C102.1@2365,117.21
EN_PRE_BUCK: J3.4 J7.114 R155.2 R157.2 | length 2232.7
  Signal Layer 1 w10: J3.4@450,2450 498,2498 995,2498 1068,2425 1068,2380 1388,2060 1784,2060 1908,1936 2062,1936 v1(2072,1946)
  Bottom Layer w10: J3.4@450,2450 598.62,2450 R157.2@598.62,2375 ; v1(2072,1946) 2086.83,1960.83 J7.114@2169.74,1960.83
EN_SEQ_LDOA: C113.1 J7.58 R101.1 R116.2 U1.22 | length 1860.8
  Top Layer w4: v1(1081,696.5) 1081,716 1092,727 1150,727 1161,738 1161,752 1150,763 1150,783 1163,796 1184,796 1195.1,807.1 U1.22@1195.1,823.54
  Signal Layer 1 w6: v1(1081,696.5) 1081,672 1115,638 1723,638 1809,724 1809,788.28 1847.6,826.87 1928.87,826.87 1985,883 1985,953.87 v1(2075.13,1044)
  Bottom Layer w6: R101.1@1042.65,584.91 1081,623.25 v1(1081,696.5) ; v1(2075.13,1044) 2110.06,1078.94 J7.58@2169.74,1078.94
  Bottom Layer w10: R116.2@993,505.62 1010.22,522.84 C113.1@1042.65,522.84 R101.1@1042.65,580.6
EN_SEQ_LDOB: C109.1 J7.42 R97.1 R112.2 U3.22 | length 3434.5
  Top Layer w4: v1(230,1335) 230,1315 244.88,1300.12 U3.22@258.54,1300.12
  Signal Layer 1 w4: v1(230,1335) 220,1345 187,1345 155,1313 155,1267 232,1190
  Signal Layer 1 w6: 232,1190 232,1121 136,1025 136,655 v1(251,540) 332,459 1739,459 1783,503 2038,503 2095,560 2095,818.94 v1(2103.03,826.97)
  Bottom Layer w6: v1(2103.03,826.97) J7.42@2169.74,826.97
  Bottom Layer w10: R112.2@232,482.24 C109.1@282,482.24 R97.1@282,540 v1(251,540)
EN_SEQ_LS1: C101.1 J7.92 R89.2 R104.2 U2.D2 | length 1225.3
  Top Layer w4: U2.D2@1600.16,1653.98 v1(1600.16,1674.84)
  Top Layer w6: R104.2@1299,1692.99 C101.1@1349,1692.99 ; R89.2@1349,1750.74 C101.1@1349,1692.99 ; v1(1600.16,1794) 1600.16,1744.16 1590,1734 1448,1734 1441,1727 1441,1709 1424.99,1692.99 C101.1@1349,1692.99
  Signal Layer 1 w6: v1(1600.16,1794) 1692,1794 1734,1752 1825,1752 1886,1691 2032.74,1691 v1(2109.37,1614.37)
  Signal Layer 2 w6: v1(1600.16,1674.84) v1(1600.16,1794) v1@1600.16,1794.84
  Bottom Layer w6: v1(2109.37,1614.37) J7.92@2169.74,1614.37
EN_SEQ_LS2: C100.1 J7.22 R88.2 R103.2 U4.D2 | length 987.9
  Top Layer w10: v1(1864.13,269.13) U4.D2@1895.71,269.13
  Signal Layer 1 w6: v1(1864.13,269.13) 2065.13,269.13 2241.99,445.99 v1(2241.99,512.01)
  Bottom Layer w6: J7.22@2169.74,512.01 v1(2241.99,512.01) 2380,374 R88.2@2444,374 C100.1@2444,316.24 R103.2@2394,316.24
EN_SEQ_LS3: C99.1 J7.94 R87.2 R102.2 U6.D2 | length 1073.8
  Top Layer w6: R102.2@1398.79,1864.26 C99.1@1448.79,1864.26 v1(1448.79,1893) R87.2@1448.79,1922.01
  Top Layer w10: U6.D2@1759.68,1885 U6.D2@1759.53,1884.84 1759.53,1885.03 v1(1809,1885)
  Signal Layer 1 w6: v1(1448.79,1893) 1470.79,1915 1793,1915 1809,1899 v1(1809,1885) 1809,1812 1845,1776 2022.28,1776 2039.87,1758.4 2039.87,1718 v1(2112.01,1645.87)
  Bottom Layer w6: v1(2112.01,1645.87) J7.94@2169.74,1645.87
GND: C1.2 C2.2 C3.2 C4.2 C5.2 C6.2 C7.2 C8.2 C9.2 C10.2 C11.2 C12.2 C13.2 C14.2 C15.2 C16.2 C17.2 C18.2 C19.2 C20.2 C21.2 C23.2 C24.2 C25.2 C26.2 C27.2 C28.2 C29.2 C30.2 C31.2 C32.2 C33.2 C34.2 C35.2 C36.2 C37.2 C38.2 C39.2 C40.2 C41.2 C42.2 C43.2 C44.2 C45.2 C46.2 C48.2 C49.2 C50.2 C52.2 C53.2 C54.2 C55.2 C56.2 C57.2 C58.2 C59.2 C60.2 C61.2 C63.2 C64.2 C65.2 C66.2 C69.2 C70.2 C71.2 C72.2 C73.2 C74.2 C75.2 C76.2 C77.2 C78.2 C80.2 C82.2 C83.2 C84.2 C85.2 C86.2 C87.2 C88.2 C89.2 C90.2 C91.2 C92.2 C94.2 C95.2 C96.2 C97.2 C98.2 C99.2 C100.2 C101.2 C102.2 C103.2 C104.2 C105.2 C106.2 C107.2 C108.2 C109.2 C110.2 C111.2 C112.2 C113.2 C114.2 C115.2 J1.2 J1.3 J2.2 J3.5 J3.6 J4.5 J4.6 J5.2 J6.2 J6.3 J7.1 J7.8 J7.10 J7.12 J7.13 J7.15 J7.17 J7.25 J7.27 J7.29 J7.30 J7.31 J7.32 J7.33 J7.34 J7.45 J7.50 J7.51 J7.57 J7.59 J7.60 J7.61 J7.69 J7.71 J7.74 J7.76 J7.87 J7.89 J7.90 J7.91 J7.96 J7.98 J7.99 J7.100 J7.101 J7.102 J7.104 J7.105 J7.106 J7.107 J7.108 J7.109 J7.110 J7.111 J7.113 Q1.2 Q3.2 Q4.2 Q5.2 Q6.2 Q7.2 Q8.2 Q9.2 R39.1 R41.1 R79.1 R102.1 R103.1 R104.1 R105.1 R106.1 R107.1 R108.1 R109.1 R110.1 R111.1 R112.1 R113.1 R114.1 R115.1 R116.1 R118.1 R157.1 S1.1 S1.2 S2.1 S2.2 U1.3 U1.8 U1.14 U1.15 U1.17 U1.34 U1.40 U1.41 U2.D1 U3.3 U3.8 U3.14 U3.15 U3.17 U3.34 U3.40 U3.41 U4.D1 U5.3 U5.4 U5.5 U5.8 U5.9 U5.10 U6.D1 U7.3 U7.4 U7.5 U7.8 U7.9 U7.10 U8.1 U8.3 U8.9@715.63,307.09 U9.4 U9.8 U9.11@1346.48,293.9 | length 11994.8
  Top Layer w4: U8.3@725.47,269.69 725.47,256.53 732.03,249.97 750.23,249.97 v1(763.15,237.05)
  Top Layer w6: U1.40@1346.67,990.87 1346.67,998.31 1355.36,1007 v1(1364,1007)
  Top Layer w7: v2(1250.22,920) U1.41@1289.59,959.37 ; U1.34@1346.67,896.38 1382.62,896.38 1397,882
  Top Layer w7.6: U3.41@331.38,1268.62 U3.17@331.38,1341.46 ; v2(355,1245) 394.37,1205.63 U3.3@451.46,1205.63 ; U3.41@394.37,1284.37 U3.8@451.46,1284.37
  Top Layer w7.8: U1.17@1153.76,896.38 U1.41@1226.59,896.38 ; U1.15@1153.76,927.87 U1.41@1242.34,927.87 ; U1.14@1153.76,943.62 U1.41@1226.59,943.62 ; U1.41@1273.84,896.38 U1.34@1346.67,896.38 ; 1422.04,1051.04 1434,1063 1437,1060 v1@1446,1060
  Top Layer w10: U3.40@429.39,1151 v1(446,1151) ; R104.1@1299,1645.74 C101.2@1349,1645.74 ; R102.1@1398.79,1817.01 C99.2@1448.79,1817.01 v1(1480.99,1817.01) ; U2.D1@1619.84,1653.98 1628.87,1663 ; 1633.13,1663 1628.87,1663 ; C11.2@1680,1670.94 1636.81,1670.94 1628.87,1663 ; U6.D1@1759.53,1865.16 v1(1789.84,1865.16) ; C42.2@1866,334.58 1866,301 1878.18,288.82 U4.D1@1895.71,288.82
  Top Layer w14: S2.1@310.83,1923.74 S2.2@539.17,1923.74 ; C114.2@1065.56,936 1139,936 ; S1.2@1201.38,1671.77 S1.1@1201.38,1900.12 ; 1633.13,1663 C11.2@1672.06,1663 ; Q9.2@2389.49,3302.4 v1(2427.4,3302.4) ; Q6.2@2392.24,2526 v1(2434,2526) ; Q1.2@2393.23,1112.4 v1(2432.6,1112.4) ; Q8.2@2395.55,3034.19 v1(2439.19,3034.19) ; Q7.2@2397.97,2775 v1(2450,2775) ; Q3.2@2400.51,1770 v1(2440,1770) ; Q4.2@2406.14,2012.4 v1(2442.4,2012.4) ; Q5.2@2406.93,2262.4 v1(2442.6,2262.4) ; R118.1@2408.62,930 v1(2440,930)
  Top Layer w16: v2(1385.85,293.9) 1406.48,314.53 R79.1@1406.48,365.83
  Top Layer w20: 1139,936 1234.22,936 1242.34,927.87 v2(1250.22,920) ; v1(1139,2367) C63.2@1183.5,2367 ; v1(1169,3100) C80.2@1223.72,3100 ; C1.2@1236.38,1485 C2.2@1286.5,1485 ; C101.2@1349,1645.74 1384.74,1645.74 v1(1406,1667) 1467,1667 ; C9.2@1488.07,1670.94 C9.2@1493.5,1676.38 ; C11.2@1672.06,1663 C11.2@1680,1670.94 C11.2@1680,1676.38 ; C42.2@1886,354.58 v1(1886,419)
  Top Layer w30: C24.2@1008,976.5 1054.72,976.5 1064.53,966.69 C114.2@1064.53,934.97
  Top Layer w40: C23.2@1018,778 1063,778 1076,765 C23.2@1021.5,765
  Top Layer w50: 961.5,984.5 C24.2@1009,984.5 ; C2.2@1286.5,1485 C5.2@1430,1485
  Bottom Layer w7.6: v1(255,1663) R41.1@255,1628.62 R39.1@295,1628.62
  Bottom Layer w10: v1(1232,2250) 1232,2264.21 R108.1@1242.62,2274.83 C105.2@1242.62,2324.83 ; v1(1253,2938.66) R107.1@1291.34,2977 ; U9.8@1346.48,238.78 v2(1346.48,269.29) U9.11@1346.48,293.9 ; U9.11@1366.16,313.58 U9.4@1366.16,349.02 ; U9.11@1370.1,270.28 1499.82,270.28 ; R103.1@2394,269 C100.2@2444,269
  Bottom Layer w14: R107.1@1291.34,2977 C104.2@1291.34,3027 ; C17.2@1555.38,1169.62 C17.2@1570,1155
  Bottom Layer w16: 1934.72,187 J7.1@1944.26,196.54
  Bottom Layer w20: C50.2@395,1420 413.54,1401.46 v1(430,1401.46) ; J3.5@450,2350 473.62,2326.38 R157.1@600,2326.38 ; C7.2@1413,858.5 1438,833.5 v1(1438,814) ; v1(1791,1005) 1811.55,984.45 J7.51@1944.26,984.45 ; v1(1848,658) 1868.01,637.99 J7.29@1944.26,637.99 2009.98,637.99 v1(2024.68,652.7) ; v1(1856,1295) 1883.09,1267.91 J7.69@1944.26,1267.91 ; v1(1860,1088) 1869.06,1078.94 J7.57@1944.26,1078.94 ; v1(1862,1601) 1875.37,1614.37 J7.91@1944.26,1614.37 ; v1(1864,1133) 1872.93,1141.93 J7.61@1944.26,1141.93 ; v1(1866,1567) 1881.62,1551.38 J7.87@1944.26,1551.38 ; v1(1875,686) 1889.98,700.98 J7.33@1944.26,700.98 2019.02,700.98 v1(2023,697) ; v1(1875,865) 1875,866.16 1898.8,889.96 J7.45@1944.26,889.96 ; v1(1876,1754) 1893.85,1771.85 J7.101@1944.26,1771.85 1991.15,1771.85 2007,1756 v1(2017,1756) ; v1@1882.66,1866.34 J7.107@1944.26,1866.34 ; v1(1885,385) 1999,385 ; v1(1886,187) 1934.72,187 ; v1(1886,419) v1@2005,419 ; 1886,608 1944.26,608 2002,608 ; v1(1886.33,1929.33) J7.111@1944.26,1929.33 ; 1888,450 2011,450 v1(2038,423) ; v1@1889,575 J7.25@1944.26,575 v1(2000,575) ; v1(1889,1109) J7.59@1944.26,1109 ; v1@1890.41,1299.41 J7.71@1944.26,1299.41 ; v1@1891.13,1582.87 J7.89@1944.26,1582.87 ; v1(1898,1740) v1(1990,1740) ; v1(1901.24,670) 1944.26,670 v1@1998,670 ; J7.31@1945.78,671 v1(1999,671) ; v1(1998,1584) J7.89@1944.26,1584 ; v1(1998,1613) 1996.63,1614.37 J7.91@1944.26,1614.37 ; v1@1998.41,1299.41 J7.71@1944.26,1299.41 ; v1@2000,1109 v1(1999,1109) J7.59@1944.26,1109 ; v1(2004.83,1960.83) J7.113@1944.26,1960.83 J7.111@1944.26,1929.33 ; v1(2011.83,1897.83) J7.109@1944.26,1897.83 ; v1(2012,1560) 2003.38,1551.38 J7.87@1944.26,1551.38 ; v1(2013,1850) 1997.84,1834.84 J7.105@1944.26,1834.84 J7.107@1944.26,1866.34 ; v1(2026,1293) 2000.91,1267.91 J7.69@1944.26,1267.91 ; v1(2027,1142) J7.61@1944.26,1141.93 ; v1(2031,1113) 2031,1098 2011.94,1078.94 J7.57@1944.26,1078.94 ; v1(2101,1702) 2125.64,1677.36 J7.96@2169.74,1677.36 J7.98@2169.74,1708.86 J7.100@2169.74,1740.35 J7.102@2169.74,1771.85 J7.104@2169.74,1803.35 J7.106@2169.74,1834.84 J7.108@2169.74,1866.34 J7.110@2169.74,1897.83 2114.83,1897.83 v1(2103,1886) ; J7.10@2169.77,323 v1(2223,323) ; J7.50@2169.74,952.95 2219.05,952.95 v1(2232,940) ; J7.60@2169.74,1110.43 2217.43,1110.43 v1(2238,1131) ; J7.74@2169.74,1330.91 2218.91,1330.91 v1(2224,1336) ; J7.76@2169.74,1362.4 v1(2224.6,1362.4) ; v1@2225.51,669.49 J7.32@2169.74,669.49 ; v1(2242,305) 2228.54,291.54 J7.8@2169.74,291.54 J7.10@2169.74,323.03 J7.12@2169.74,354.53 2228.47,354.53 v1(2242,341) ; v1(2263,688) 2250.02,700.98 J7.34@2169.74,700.98 J7.32@2169.74,669.49 ; v1(2264,652) 2249.99,637.99 J7.30@2169.74,637.99 J7.32@2169.74,669.49 ; R105.1@2422.99,67.21 C102.2@2422.99,117.21 v1(2444,138.22) C100.2@2444,269 ; J7.57@1944.26,1078.94 J7.59@1944.26,1109 ; J7.59@1944.26,1109 J7.59@1944.26,1110.43 J7.61@1944.26,1141.93 ; J7.69@1944.26,1267.91 J7.71@1944.26,1299.41 ; J7.87@1944.26,1551.38 J7.89@1944.26,1582.87 ; J7.89@1944.26,1582.87 J7.89@1944.26,1584 ; J7.89@1944.26,1584 J7.91@1944.26,1614.37 ; J7.107@1944.26,1866.34 J7.109@1944.26,1897.83 ; J7.109@1944.26,1897.83 J7.111@1944.26,1929.33
  Bottom Layer w24: C95.2@1500.1,234.45 1500.1,270.28 C94.2@1500.1,304.45
  Bottom Layer w30: v1(207,435) R112.1@232,435 296.26,435 R109.1@337,475.74 848.99,475.74 858.36,466.38 R115.1@894,466.38 933.62,466.38 C112.2@944,476.76 962.38,458.38 R116.1@993,458.38 ; v1@993,395 R116.1@993,458.38 ; C113.2@1042.65,475.6 1025.43,458.38 R116.1@993,458.38 ; C96.2@1187.85,344.45 1187.85,313.07 C92.2@1221.48,279.45
  Bottom Layer w40: C92.2@1221.48,279.45 U9.11@1332.03,279.45 ; C54.2@1489.23,2630 C59.2@1612.18,2630 ; 1500.1,270.28 1707.28,270.28 1833,396 ; 1887,436 1873,436 ; J7.17@1944.26,443 1880,443 1873,436 ; 1996,396 1833,396 ; 1833,396 1873,436
  Bottom Layer w50: C31.2@761,1171 C29.2@761,1251 ; C89.2@885.63,252.09 969,252.09 1006.09,289.17 C91.2@1015,289.17 ; C25.2@1107,772 C25.2@1125,790 ; C97.2@1216.48,489.45 C98.2@1296.48,489.45 C85.2@1381.48,489.45 C86.2@1461.48,489.45 C87.2@1541.48,489.45 1671.45,489.45 1772,590 ; C6.2@1350,1485 C4.2@1430,1485
  Bottom Layer w60: 1030,772 C25.2@1099,772 ; 1772,590 2005,590 ; J7.27@1944.26,606.5 1944.26,608 J7.29@1944.26,637.99 J7.31@1944.26,669.49 1944.26,670 1944.26,680.74
  other v1: 1848,168 1844,194 575,200 625,200 550,225 600,225 650,225 930,243 948,265 931,289.17 2004,390 993,393 1864,402 993,420 2006,420 257,435 1860,577 1887,577 227,623 261,623 197,626 194,664 2226,669 194,698 194,731 1032.54,753 1058,761.24 1039,779 1064,790 1475,812 1508,816 231,824 260,825 1530,830 1510,847 795,865 815,885 780,887 983,970 250,974 278,974 952,977 971,999 1413,1055 1447,1057 1065,1066 1448,1085 1065,1094 690,1120 730,1120 765,1120 1065,1121 1608,1143 1065,1150 727,1165 1608,1173 725,1195 1559,1201 1595,1206 1404,1214 1535,1220 727,1225 1579,1227 685,1235 1607,1237.32 1549,1243 1409,1248 715,1250 690,1260 725,1280 1890,1300 1999,1300 456,1419 459,1448 129,1456 130,1493 169,1495 1210,1523 1263.36,1523 1357.5,1533.32 1395.3,1533.32 1288.1,1536.3 1240.76,1538 1891,1583 2127,1584 1574,1676 1518.7,1685.32 1549,1691 1201.38,1790 1885,1866.34 425,1923.74 1550,2125 1525,2150 1575,2150 1550,2175 1525,2200 1575,2200 1550,2225 1525,2250 1575,2250 1550,2275 1305,2495 1550,2525 1525,2550 1575,2550 1550,2575 1525,2600 1575,2600 1550,2630 1525,2650 1575,2650 1550,2675 1525,2700 1575,2700 1550,2725 1525,2825 1575,2825 1625,2825 1550,2850 1600,2850 1650,2850 1525,2875 1625,2875 1575,2877.01 1344,3205 1525,3400 1575,3400 1625,3400 1550,3425 1600,3425
  other v2: 1307.11,293.9 693.98,307.09 737.29,307.09 1346.48,318.5 1250.22,860.94 1191.16,920 1309.27,920 1250.22,979.05 355,1185.95 295.95,1245 414.06,1245 355,1304.06
HiCurrent_PG: J7.115 R60.2 R132.1 U5.16 | length 2280.9
  Top Layer w4: v1(1253,2406) 1259.87,2399.13 1309.31,2399.13 U5.16@1309.31,2400.16
  Top Layer w6: v1(1884,1992) 2041,1992 2067,1966 2124,1966 2225,2067 v1(2225,2085)
  Signal Layer 1 w6: v1(1253,2406) 1283,2376 1308,2376 1390,2294 1791,2294 1864,2221 1864,2012 v1(1884,1992) ; v1(2225,2085) 2225,2510 v1(2374,2659)
  Bottom Layer w6: R60.2@1137.89,2435 1137.89,2420.11 1152,2406 v1(1253,2406)
  Bottom Layer w10: v1@1884.32,1992.32 J7.115@1944.26,1992.32 ; R132.1@2350.14,2701.79 2374,2677.93 v1(2374,2659)
HOT_RESETz_A: R8.1 R29.2 S1.3 S1.4 U1.11 | length 1211.4
  Top Layer w4: v1@1124,1007 1140.13,990.87 U1.11@1153.76,990.87
  Top Layer w6: R29.2@940.62,1585 1044,1585 ; S1.4@1043.9,1671.77 1043,1670.87 1045,1668.87 v1(1045,1541)
  Top Layer w14: S1.4@1043.9,1671.77 S1.3@1043.9,1900.12
  Signal Layer 1 w6: v1(1045,1541) 1148,1541 1188,1501 1188,1444 1137,1393 1137,1031 1124,1018 v1@1124,1007
  Bottom Layer w4: R8.1@1096.83,1016.79 1114.21,1016.79 v1@1124,1007
  other v1: 1124,1009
